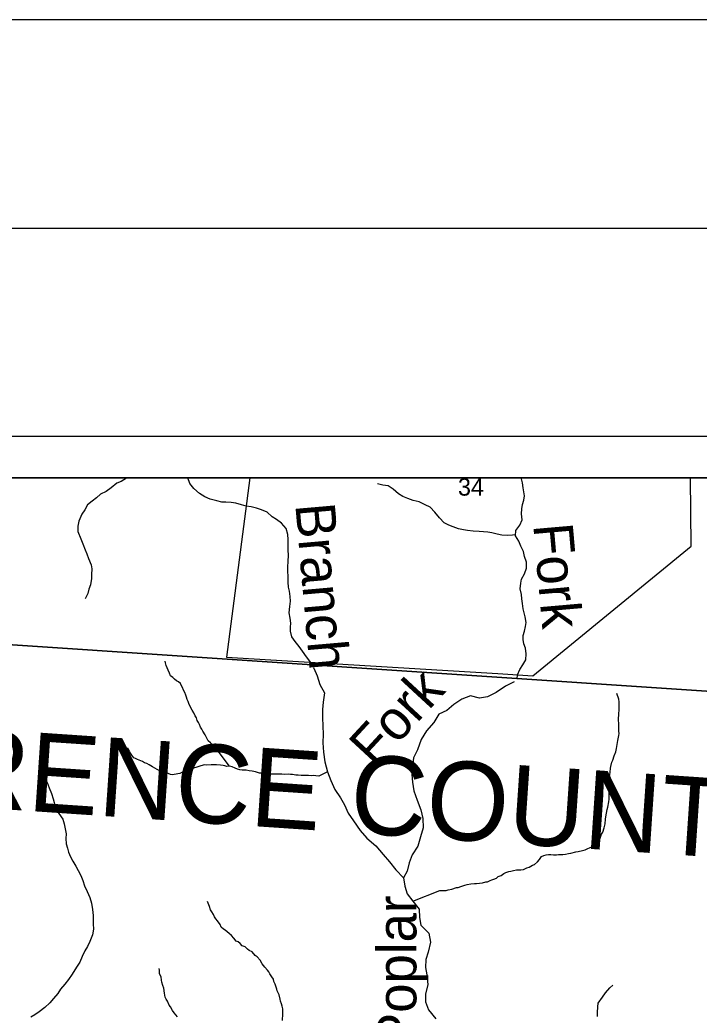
# Model space of a CAD drawing. Extents: x 0 to 82.7, y -0.2 to 22.
# Drawn here: x 3.743 to 5.374, y 19.61 to 22 of the extents above; entities that cross this region are included whole.
import ezdxf

# ---------------------------------------------------------------- set-up
doc = ezdxf.new("R2010")
doc.units = 0
for name, color, linetype in [('GM_X_County_Road', 7, 'Continuous'), ('GM_X_County_Text', 7, 'Continuous'), ('GM_X_Minor_River', 7, 'Continuous'), ('GM_X_Minor_River_Text', 7, 'Continuous'), ('GM_X_Section_Text', 7, 'Continuous'), ('GM_X_Township_Text', 7, 'Continuous'), ('SH_Border', 7, 'Continuous'), ('SH_Cut_Line', 7, 'Continuous'), ('SH_Data', 7, 'Continuous')]:
    doc.layers.add(name, color=color, linetype=linetype)

msp = doc.modelspace()

# ---------------------------------------------------------------- linework, layer by layer
at = {"layer": 'GM_X_County_Road'}
msp.add_lwpolyline([(5.3528, 20.9), (4.2954, 20.9), (4.2394, 20.4693), (4.8904, 20.4302), (4.9747, 20.425), (5.3548, 20.7363)], close=True, dxfattribs=at)
at = {"layer": 'GM_X_Minor_River'}
for points in [[(4.0003, 20.9), (3.9992, 20.8993), (3.9859, 20.8914), (3.9756, 20.8873), (3.9624, 20.8767), (3.9502, 20.8673), (3.9369, 20.8609), (3.927, 20.8526), (3.9168, 20.8443), (3.9054, 20.8356), (3.8989, 20.8235), (3.8921, 20.8129), (3.8844, 20.7966), (3.8825, 20.7841), (3.8821, 20.7716), (3.8892, 20.7537), (3.8945, 20.7416), (3.9001, 20.7275), (3.9042, 20.718), (3.908, 20.7066), (3.9144, 20.6918), (3.9158, 20.6815), (3.9147, 20.6679), (3.9154, 20.6584), (3.9127, 20.6436), (3.9089, 20.6326), (3.9062, 20.6228), (3.8997, 20.6095)], [(4.4466, 20.4505), (4.4416, 20.4572), (4.4314, 20.4706), (4.4216, 20.4839), (4.4133, 20.4953), (4.4039, 20.5071), (4.3964, 20.5189), (4.3926, 20.5318), (4.3926, 20.5416), (4.3934, 20.5511), (4.392, 20.5636), (4.3897, 20.5765), (4.3909, 20.591), (4.3925, 20.6038), (4.3918, 20.6156), (4.3903, 20.6278), (4.3884, 20.6376), (4.387, 20.6498), (4.3874, 20.6634), (4.3867, 20.6763), (4.3863, 20.6862), (4.3871, 20.7006), (4.3879, 20.7139), (4.3872, 20.7275), (4.3876, 20.74), (4.3873, 20.7522), (4.3866, 20.7643), (4.3825, 20.7784), (4.3712, 20.7913), (4.3594, 20.8005), (4.3489, 20.8066), (4.3368, 20.818), (4.3228, 20.8234), (4.3111, 20.8276), (4.2986, 20.8303), (4.2865, 20.8326), (4.2755, 20.8353), (4.2619, 20.8395), (4.2505, 20.8411), (4.2376, 20.8419), (4.2278, 20.8423), (4.216, 20.8454), (4.2001, 20.8493), (4.1873, 20.855), (4.1741, 20.863), (4.1608, 20.8744), (4.151, 20.887), (4.146, 20.9)], [(4.9367, 20.4178), (4.9381, 20.4269), (4.9438, 20.4398), (4.9507, 20.4511), (4.9575, 20.4636), (4.9587, 20.4776), (4.9569, 20.4917), (4.9531, 20.5016), (4.9513, 20.5122), (4.9517, 20.5221), (4.9548, 20.5319), (4.9574, 20.5433), (4.9586, 20.5527), (4.9564, 20.5668), (4.9541, 20.5763), (4.9515, 20.5858), (4.9497, 20.5983), (4.9486, 20.6097), (4.9471, 20.6199), (4.9441, 20.6336), (4.9461, 20.6476), (4.9472, 20.6571), (4.9545, 20.67), (4.9591, 20.6836), (4.9591, 20.6977), (4.9546, 20.7113), (4.9524, 20.7238), (4.9456, 20.7364), (4.9411, 20.7485), (4.9332, 20.7607), (4.934, 20.7736), (4.9431, 20.7865), (4.9492, 20.7997), (4.9478, 20.8138), (4.9486, 20.8255), (4.9501, 20.8365), (4.9528, 20.8468), (4.9544, 20.857), (4.9533, 20.8669), (4.9518, 20.8763), (4.9495, 20.8881), (4.9473, 20.8976), (4.9467, 20.9)], [(4.9334, 20.7633), (4.926, 20.7626), (4.9139, 20.7616), (4.8999, 20.7627), (4.8893, 20.7651), (4.8764, 20.7681), (4.8666, 20.7701), (4.856, 20.7709), (4.8461, 20.7717), (4.8317, 20.7721), (4.8181, 20.7737), (4.8082, 20.7752), (4.7965, 20.7779), (4.7833, 20.7829), (4.7727, 20.7867), (4.7621, 20.7925), (4.7504, 20.8043), (4.7394, 20.8176), (4.7281, 20.8302), (4.716, 20.8359), (4.7016, 20.8428), (4.6876, 20.8459), (4.6744, 20.8505), (4.6623, 20.8555), (4.6521, 20.8619), (4.6389, 20.873), (4.6275, 20.8814), (4.6147, 20.8826), (4.6018, 20.8857)], [(4.246, 20.2082), (4.2116, 20.2538), (4.2056, 20.2588), (4.2007, 20.2642), (4.1951, 20.2685), (4.1914, 20.2765), (4.1876, 20.283), (4.1824, 20.2918), (4.1798, 20.2968), (4.1768, 20.3014), (4.1746, 20.3079), (4.1717, 20.3132), (4.1691, 20.3178), (4.1672, 20.3239), (4.1639, 20.3289), (4.1605, 20.3358), (4.1568, 20.3423), (4.1531, 20.3496), (4.149, 20.3584), (4.1472, 20.3629), (4.145, 20.3679), (4.1432, 20.3733), (4.1417, 20.3782), (4.1395, 20.3847), (4.1361, 20.3905), (4.1336, 20.3969), (4.1306, 20.4023), (4.1287, 20.4065), (4.1242, 20.4107), (4.1193, 20.4131), (4.1141, 20.4166), (4.1103, 20.4208), (4.1051, 20.4251), (4.1021, 20.4316), (4.0988, 20.4381), (4.0969, 20.4438), (4.0947, 20.4495), (4.0925, 20.456), (4.0918, 20.4602)], [(4.4484, 20.4443), (4.4489, 20.4436), (4.4571, 20.425), (4.4634, 20.4037), (4.4742, 20.3839), (4.4714, 20.3619), (4.4698, 20.3444), (4.4693, 20.325), (4.4703, 20.3038), (4.4713, 20.2848), (4.4708, 20.2639), (4.4718, 20.2418), (4.4754, 20.2187), (4.4813, 20.1947), (4.4895, 20.1734), (4.4992, 20.1521), (4.5127, 20.1319), (4.5225, 20.1147), (4.5315, 20.0949), (4.5442, 20.0766), (4.5604, 20.0538), (4.5762, 20.0351), (4.5973, 20.0167), (4.6154, 19.9961), (4.6304, 19.9786), (4.6458, 19.9588), (4.6643, 19.9397), (4.6672, 19.9195), (4.6731, 19.9013), (4.6863, 19.8841), (4.7017, 19.8647), (4.7023, 19.8449), (4.7056, 19.8259), (4.7252, 19.8068), (4.7292, 19.7855), (4.723, 19.7616), (4.718, 19.7438), (4.7171, 19.7241), (4.7204, 19.707), (4.7229, 19.6834), (4.717, 19.6603), (4.7173, 19.6417), (4.724, 19.623), (4.742, 19.6013)], [(4.9296, 20.4104), (4.9093, 20.3998), (4.8865, 20.3851), (4.8655, 20.3742), (4.8462, 20.3709), (4.825, 20.3771), (4.8044, 20.3689), (4.785, 20.356), (4.7678, 20.3413), (4.7488, 20.3331), (4.7366, 20.313), (4.719, 20.2926), (4.7067, 20.2721), (4.6974, 20.2475), (4.6882, 20.2278), (4.6854, 20.2062), (4.6842, 20.1883), (4.6859, 20.1693), (4.6892, 20.1488), (4.697, 20.126), (4.7056, 20.1028), (4.7107, 20.0826), (4.7117, 20.0602), (4.7048, 20.0386), (4.6989, 20.0162), (4.6848, 19.9954), (4.6778, 19.9761), (4.6731, 19.956), (4.6643, 19.9397)], [(5.1735, 20.242), (5.1752, 20.2503), (5.1776, 20.2644), (5.1788, 20.2697), (5.1808, 20.2814), (5.182, 20.286), (5.1813, 20.2921), (5.181, 20.2978), (5.1807, 20.3065), (5.1808, 20.3111), (5.1805, 20.3175), (5.1805, 20.3228), (5.181, 20.3312), (5.1816, 20.3456), (5.182, 20.3502), (5.1821, 20.357), (5.1818, 20.3627), (5.1811, 20.3692), (5.1763, 20.3822)], [(4.4813, 20.1947), (4.4608, 20.1838), (4.454, 20.1846), (4.4471, 20.1858), (4.4426, 20.1848), (4.4361, 20.1852), (4.4312, 20.1857), (4.4187, 20.1858), (4.4115, 20.1867), (4.4058, 20.1867), (4.3978, 20.188), (4.3925, 20.1881), (4.388, 20.1889), (4.3789, 20.1882), (4.3724, 20.1887), (4.3656, 20.1888), (4.358, 20.1889), (4.3523, 20.1886), (4.3451, 20.189), (4.3398, 20.1895), (4.3311, 20.19), (4.3258, 20.1908), (4.3182, 20.1913), (4.3091, 20.1941), (4.3046, 20.1949), (4.3004, 20.1957), (4.2932, 20.1969), (4.2864, 20.1981), (4.2811, 20.1986), (4.277, 20.1986), (4.2709, 20.1995), (4.2656, 20.2007), (4.2603, 20.203), (4.2528, 20.2065), (4.246, 20.2082), (4.2399, 20.2071), (4.2353, 20.2087), (4.2308, 20.2095), (4.2247, 20.2103), (4.2153, 20.2108), (4.2027, 20.211), (4.1913, 20.2104), (4.186, 20.2108), (4.1777, 20.2086), (4.1681, 20.2053), (4.1601, 20.2028), (4.1548, 20.2002), (4.1502, 20.1987), (4.1441, 20.1969), (4.1388, 20.1955), (4.132, 20.1925), (4.127, 20.1903), (4.1137, 20.1878), (4.1095, 20.1875), (4.1046, 20.1883), (4.0951, 20.1918), (4.0902, 20.1934), (4.0819, 20.1966), (4.0774, 20.1978), (4.0725, 20.2001), (4.0668, 20.2028), (4.0612, 20.2063), (4.0533, 20.211), (4.0476, 20.2145), (4.0423, 20.2161), (4.0378, 20.2188), (4.0333, 20.2207), (4.0257, 20.2243), (4.0208, 20.2262), (4.0167, 20.2282), (4.0118, 20.2343), (4.0088, 20.2389), (4.0062, 20.2431), (4.0044, 20.2473), (4.0018, 20.2519)], [(4.6863, 19.8841), (4.7516, 19.9091), (4.7569, 19.9094), (4.7668, 19.9097), (4.7717, 19.9108), (4.7801, 19.9122), (4.7912, 19.9162), (4.7957, 19.9169), (4.8018, 19.9191), (4.8064, 19.9206), (4.8117, 19.9224), (4.817, 19.9239), (4.8254, 19.9253), (4.8345, 19.9263), (4.8395, 19.9262), (4.8467, 19.9269), (4.8539, 19.928), (4.8619, 19.9298), (4.8661, 19.9305), (4.8718, 19.9334), (4.876, 19.9349), (4.8813, 19.9363), (4.887, 19.9393), (4.8912, 19.9427), (4.8985, 19.9456), (4.905, 19.9505), (4.9096, 19.9527), (4.9168, 19.9549), (4.9214, 19.956), (4.9278, 19.9574), (4.9351, 19.9588), (4.9457, 19.9587), (4.9521, 19.9598), (4.9602, 19.9638), (4.9655, 19.9657), (4.9739, 19.9701), (4.9785, 19.9716), (4.9861, 19.9783), (4.9907, 19.984), (4.9958, 19.9911), (5.0007, 19.9934), (5.0064, 19.9952), (5.0125, 19.9962), (5.0178, 19.9962), (5.0246, 19.9953), (5.0315, 19.9952), (5.0364, 19.9959), (5.0463, 19.9962), (5.0527, 19.9969), (5.0603, 19.9979), (5.066, 19.999), (5.0782, 20.0019), (5.0831, 20.003), (5.0942, 20.0051), (5.1006, 20.0073), (5.1048, 20.0091), (5.1125, 20.0128), (5.1186, 20.015), (5.1236, 20.0207), (5.1305, 20.0263), (5.1355, 20.0323), (5.1398, 20.0448), (5.1429, 20.0493), (5.1456, 20.0599), (5.148, 20.0694), (5.1489, 20.0808), (5.1501, 20.0865), (5.153, 20.1035), (5.1546, 20.1092), (5.157, 20.1225), (5.1578, 20.1289), (5.1575, 20.1331), (5.1576, 20.1438), (5.1577, 20.1483), (5.1574, 20.1552), (5.1578, 20.1593), (5.1579, 20.1677), (5.1583, 20.1719), (5.1588, 20.1833), (5.1596, 20.1874), (5.1601, 20.1939), (5.1613, 20.203), (5.1621, 20.2072), (5.1645, 20.2178), (5.1669, 20.2223), (5.17, 20.2325), (5.1735, 20.242)], [(3.7938, 20.2), (3.8002, 20.1882), (3.8039, 20.1787), (3.8088, 20.1688), (3.8133, 20.1562), (3.8189, 20.1425), (3.823, 20.1295), (3.8259, 20.1173), (3.8308, 20.1036), (3.8368, 20.0941), (3.8462, 20.0807), (3.8492, 20.0693), (3.8521, 20.0575), (3.8539, 20.0453), (3.8535, 20.0343), (3.8545, 20.0217), (3.8571, 20.011), (3.8601, 20.0015), (3.8646, 19.9901), (3.8699, 19.9802), (3.8778, 19.9676), (3.8834, 19.9573), (3.8898, 19.9451), (3.8943, 19.9332), (3.898, 19.9203), (3.9047, 19.9066), (3.9111, 19.8925), (3.9148, 19.8791), (3.9174, 19.8635), (3.9188, 19.8495), (3.9187, 19.8396), (3.919, 19.8297), (3.9197, 19.8168), (3.9173, 19.8031), (3.9111, 19.7872), (3.9057, 19.7747), (3.8992, 19.7641), (3.8926, 19.7508), (3.8869, 19.7376), (3.8788, 19.7251), (3.8684, 19.7088), (3.8596, 19.6956), (3.8511, 19.6842), (3.8408, 19.6721), (3.8343, 19.6623), (3.8235, 19.6498), (3.8151, 19.6393), (3.8032, 19.6283), (3.7895, 19.6178), (3.7792, 19.611), (3.7696, 19.605)], [(4.3736, 19.5974), (4.3741, 19.613), (4.3746, 19.6202), (4.3747, 19.6251), (4.3728, 19.6316), (4.3714, 19.6373), (4.3688, 19.6434), (4.3677, 19.6484), (4.3652, 19.6587), (4.3633, 19.6636), (4.3607, 19.6682), (4.36, 19.6728), (4.356, 19.6846), (4.353, 19.6911), (4.352, 19.6965), (4.3482, 19.7018), (4.3434, 19.7091), (4.3408, 19.7137), (4.3374, 19.7179), (4.331, 19.7256), (4.3247, 19.7329), (4.3199, 19.7421), (4.3131, 19.7498), (4.3079, 19.7536), (4.3004, 19.7617), (4.2936, 19.7652), (4.2894, 19.7687), (4.2842, 19.7737), (4.2766, 19.7765), (4.2718, 19.7818), (4.2669, 19.7861), (4.2623, 19.7877), (4.2564, 19.7953), (4.2511, 19.8011), (4.2459, 19.8065), (4.2406, 19.81), (4.2361, 19.8142), (4.2319, 19.8165), (4.2263, 19.8215), (4.2237, 19.8277), (4.2174, 19.8369), (4.2133, 19.8411), (4.2107, 19.8461), (4.2081, 19.8518), (4.2043, 19.8579), (4.2006, 19.8633), (4.198, 19.8709), (4.1951, 19.8786), (4.1936, 19.8828)], [(4.1218, 19.6063), (4.1173, 19.6105), (4.1135, 19.6155), (4.1094, 19.6209), (4.105, 19.6301), (4.1012, 19.6343), (4.0975, 19.6435), (4.0942, 19.6481), (4.0923, 19.653), (4.0902, 19.6625), (4.0884, 19.6747), (4.0862, 19.6812), (4.084, 19.6892), (4.0833, 19.6938), (4.0823, 19.7018), (4.0786, 19.7094), (4.0786, 19.7136), (4.0779, 19.7182), (4.0772, 19.7224)], [(5.1295, 19.6066), (5.1296, 19.6164), (5.1304, 19.6297), (5.1316, 19.6392), (5.142, 19.6532), (5.1489, 19.6637), (5.1592, 19.6754), (5.1668, 19.6822)]]:
    msp.add_lwpolyline(points, dxfattribs=at)
at = {"layer": 'GM_X_Township_Text'}
msp.add_lwpolyline([(6.1272, 20.9), (2.1, 20.9), (2.1, 19.5964), (2.2742, 19.1826), (2.3145, 19.0873), (2.397, 18.8926), (2.4438, 18.782), (2.7199, 18.1299), (2.7784, 18.9951), (2.7788, 19.0007), (2.8288, 19.7415), (2.8645, 20.2693), (2.8645, 20.2703), (2.8651, 20.279), (2.884, 20.5583), (3.179, 20.5374), (3.6288, 20.5056), (5.9672, 20.3493), (5.9756, 20.3782)], close=True, dxfattribs=at)
msp.add_lwpolyline([(5.9672, 20.3493), (3.6288, 20.5056), (3.179, 20.5374), (2.884, 20.5583), (2.8651, 20.279), (2.8645, 20.2703), (2.8645, 20.2693), (2.8288, 19.7415), (2.7788, 19.0007), (2.7784, 18.9951), (2.7199, 18.1299), (3.0279, 17.3486), (3.0556, 17.2782), (3.2909, 16.7562), (3.4071, 16.476), (3.6125, 15.9807), (3.8036, 15.5496), (4.1209, 14.8338)], dxfattribs=at)
at = {"layer": 'SH_Border'}
msp.add_lwpolyline([(1.5, 21.5), (33.5, 21.5), (33.5, 0.5), (1.5, 0.5)], close=True, dxfattribs=at)
at = {"layer": 'SH_Cut_Line'}
msp.add_lwpolyline([(0, 0), (34, 0), (34, 22), (0, 22)], close=True, dxfattribs=at)
for points in [[(4.1209, 14.8338), (3.8036, 15.5496), (3.6125, 15.9807), (3.4071, 16.476), (3.2909, 16.7562), (3.0556, 17.2782), (3.0279, 17.3486), (2.7199, 18.1299), (2.7784, 18.9951), (2.7788, 19.0007), (2.8288, 19.7415), (2.8645, 20.2693), (2.8645, 20.2703), (2.8651, 20.279), (2.884, 20.5583), (3.179, 20.5374), (3.6288, 20.5056), (5.9672, 20.3493), (5.9756, 20.3782), (6.1272, 20.9), (2.1, 20.9), (2.1, 14.1)], [(8.9, 14.1), (8.9, 20.9), (6.1272, 20.9), (5.9756, 20.3782), (5.9672, 20.3493), (3.6288, 20.5056), (3.179, 20.5374), (2.884, 20.5583), (2.8651, 20.279), (2.8645, 20.2703), (2.8645, 20.2693), (2.8288, 19.7415), (2.7788, 19.0007), (2.7784, 18.9951), (2.7199, 18.1299), (3.0279, 17.3486), (3.0556, 17.2782), (3.2909, 16.7562), (3.4071, 16.476), (3.6125, 15.9807), (3.8036, 15.5496), (4.1209, 14.8338)]]:
    msp.add_lwpolyline(points, dxfattribs=at)
at = {"layer": 'SH_Data'}
for p, q in [((2, 21), (9, 21)), ((2.1, 20.9), (8.9, 20.9))]:
    msp.add_line(p, q, dxfattribs=at)

# ---------------------------------------------------------------- texts
at = {"layer": 'GM_X_County_Text'}
msp.add_text('LAWRENCE COUNTY', height=0.189394, rotation=356.1322, dxfattribs=at).set_placement((3.0295, 20.1501))
at = {"layer": 'GM_X_Minor_River_Text'}
for s, height, rotation, p in [('Branch', 0.09472, 274.9969, (4.4042, 20.8362)), ('Fork', 0.09472, 274.9967, (4.9755, 20.7877)), ('Fork', 0.0947, 47.2684, (4.5957, 20.2014)), ('Poplar', 0.0947, 89.9998, (4.6951, 19.5312))]:
    msp.add_text(s, height=height, rotation=rotation, dxfattribs=at).set_placement(p)
at = {"layer": 'GM_X_Section_Text'}
msp.add_text('34', height=0.04186, rotation=0, dxfattribs=at).set_placement((4.7949, 20.8576))

doc.saveas('drawing.dxf')
